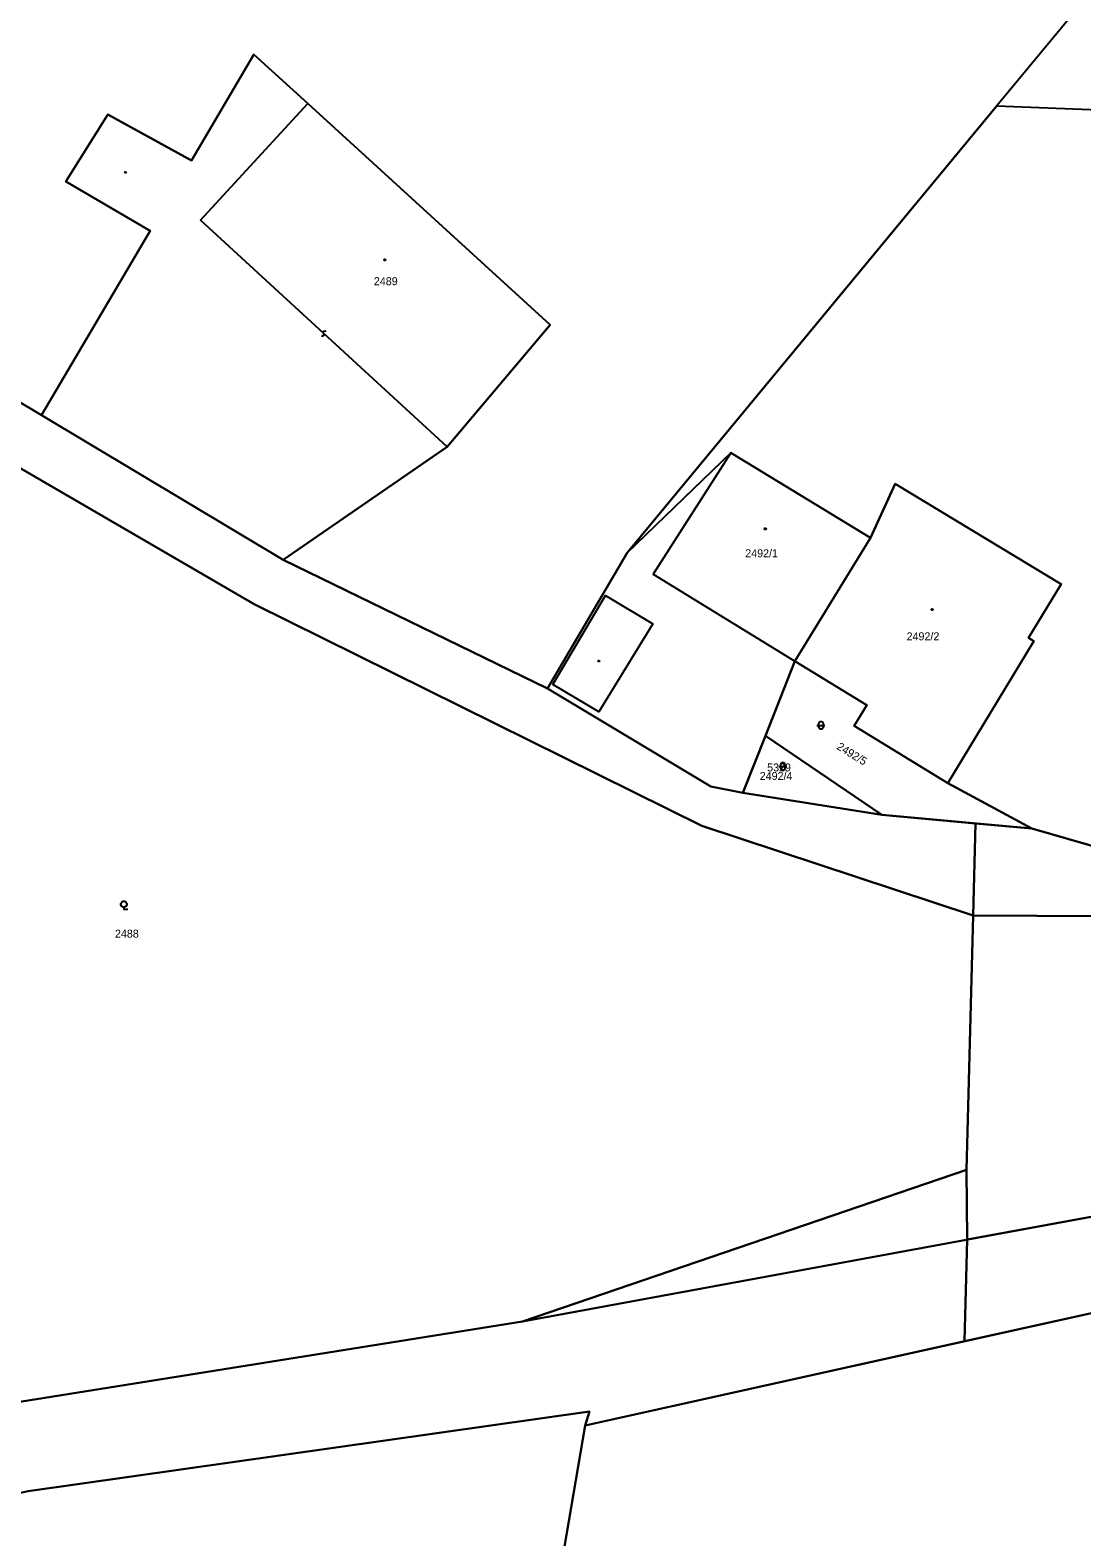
# Model space of a CAD drawing. Extents: x -439750 to -439180, y -1258684 to -1258308.
# Drawn here: x -439415 to -439362.4, y -1258429.7 to -1258354.4 of the extents above; entities that cross this region are included whole.
import ezdxf

# ---------------------------------------------------------------- set-up
doc = ezdxf.new("R2010")
doc.units = 0
doc.layers.add('KATASTER', color=7, linetype='Continuous')
doc.layers.add('UOV', color=7, linetype='Continuous')

# ---------------------------------------------------------------- blocks, each defined once
blk = doc.blocks.new('305')
blk.add_lwpolyline([(0, 0.53), (-0.19, 0.53), (-0.53, 0.72), (-0.72, 1.06), (-0.72, 1.45), (-0.53, 1.79), (-0.19, 1.98), (0.2, 1.98), (0.54, 1.79), (0.73, 1.45), (0.73, 1.06), (0.54, 0.72), (0.2, 0.53), (0.01, 0.53), (0.01, 0), (1.01, 0)])
blk = doc.blocks.new('402')
blk.add_lwpolyline([(0.09, 0.15), (0.18, 0), (0.09, -0.15), (-0.09, -0.15), (-0.18, 0), (-0.09, 0.15), (0.09, 0.15)])
blk = doc.blocks.new('316')
for points in [[(-1, 1), (0.27, 1), (1, 1)], [(-0.5, 1.5), (-0.4, 1.79), (-0.15, 1.97), (0.16, 1.97), (0.41, 1.79), (0.51, 1.5), (0.51, 0.5), (0.41, 0.21), (0.16, 0.03), (-0.15, 0.03), (-0.4, 0.21), (-0.5, 0.5), (-0.5, 1.5)]]:
    blk.add_lwpolyline(points)
blk = doc.blocks.new('2182')
blk.add_lwpolyline([(0.05, 0.75), (-0.26, 0.64), (-0.37, 0.34), (-0.23, 0.09), (0.27, -0.11), (0.37, -0.41), (0.21, -0.68), (-0.05, -0.75)])

msp = doc.modelspace()

# ---------------------------------------------------------------- linework, layer by layer
at = {"layer": 'KATASTER'}
for p, q in [((-439406.44, -1258363.89), (-439401.08, -1258358.06)), ((-439394.11, -1258375.22), (-439406.44, -1258363.89))]:
    msp.add_line(p, q, dxfattribs=at)
for points in [[(-439415.15, -1258317.05), (-439391.19, -1258328.53), (-439365.48, -1258348.34), (-439361.22, -1258351.62), (-439366.64, -1258358.17), (-439385.11, -1258380.51), (-439389.09, -1258387.3), (-439402.31, -1258380.87), (-439394.11, -1258375.22), (-439388.96, -1258369.12), (-439401.08, -1258358.06), (-439403.77, -1258355.61), (-439406.89, -1258360.91), (-439411.07, -1258358.61), (-439413.17, -1258361.96), (-439408.96, -1258364.43), (-439414.38, -1258373.64), (-439426.53, -1258366.38)], [(-439583.01, -1258405.44), (-439529.05, -1258372.98), (-439510.66, -1258363.93), (-439469.66, -1258359.58), (-439457.56, -1258358.3), (-439442.28, -1258360.05), (-439426.53, -1258366.38), (-439414.38, -1258373.64), (-439402.31, -1258380.87), (-439389.09, -1258387.3), (-439380.93, -1258392.19), (-439379.33, -1258392.51), (-439372.39, -1258393.61), (-439364.9, -1258394.3), (-439360.22, -1258395.64), (-439331.05, -1258396.01), (-439324.92, -1258395.23), (-439316.1, -1258393.08), (-439301.55, -1258387.38)], [(-439269.36, -1258377.15), (-439315.05, -1258395.8), (-439324.38, -1258397.9), (-439329.65, -1258398.85), (-439367.83, -1258398.64), (-439381.39, -1258394.16), (-439403.76, -1258383.09), (-439428.41, -1258368.76), (-439442.76, -1258364.07), (-439458.37, -1258362.23), (-439513.27, -1258367.25), (-439515.07, -1258371.54), (-439519.61, -1258372.16), (-439523.86, -1258373.74), (-439527.84, -1258376.06), (-439569.67, -1258401.31)], [(-439379.94, -1258375.52), (-439383.81, -1258381.59), (-439376.73, -1258385.93)], [(-439547.65, -1258418.05), (-439537.73, -1258410.35), (-439527.28, -1258405.47), (-439520.18, -1258404.63), (-439512.57, -1258405.64), (-439506.61, -1258407.45), (-439484.43, -1258417.81), (-439474.81, -1258422.32), (-439466.86, -1258425.16), (-439456.86, -1258427.2), (-439444.81, -1258427.42), (-439422.62, -1258423.93), (-439418.29, -1258423.4), (-439390.34, -1258418.93), (-439355.32, -1258412.49), (-439342.07, -1258411.63), (-439307.35, -1258399.88)], [(-439304.03, -1258403.29), (-439334.89, -1258413.69), (-439341.3, -1258415.85), (-439354.3, -1258417.7), (-439355.78, -1258417.92), (-439355.89, -1258417.18), (-439387.21, -1258424.13), (-439387, -1258423.44), (-439415.05, -1258427.42), (-439434.74, -1258431.72), (-439442.45, -1258432.5), (-439453.89, -1258431.74), (-439461.05, -1258431.03), (-439498.8, -1258414.92), (-439505.79, -1258411.63), (-439510.78, -1258409.92), (-439521.49, -1258405.8), (-439531.73, -1258411.37), (-439536.05, -1258413.64), (-439546.05, -1258421.31)], [(-439342.84, -1258481.76), (-439376.6, -1258488.12), (-439398.93, -1258492.76), (-439393.11, -1258458.67), (-439387.21, -1258424.13), (-439355.89, -1258417.18), (-439355.78, -1258417.92), (-439352.04, -1258443.07), (-439355.61, -1258442.12), (-439357.86, -1258441.52), (-439357.71, -1258440.96), (-439364.32, -1258439.2), (-439364.24, -1258438.91), (-439373.38, -1258436.31), (-439372.9, -1258433.44), (-439378.54, -1258432.5), (-439378.83, -1258437.55), (-439380.62, -1258447.31), (-439375.42, -1258449.5)]]:
    msp.add_lwpolyline(points, dxfattribs=at)
for points in [[(-439414.38, -1258373.64), (-439408.96, -1258364.43), (-439413.17, -1258361.96), (-439411.07, -1258358.61), (-439406.89, -1258360.91), (-439403.77, -1258355.61), (-439401.08, -1258358.06), (-439388.96, -1258369.12), (-439394.11, -1258375.22), (-439402.31, -1258380.87)], [(-439366.64, -1258358.17), (-439356.47, -1258358.58), (-439353.45, -1258359.6), (-439355.3, -1258367), (-439348.37, -1258369.41), (-439336.92, -1258372.08), (-439328.8, -1258373.21), (-439324.08, -1258371.11), (-439318.67, -1258370.58), (-439316.03, -1258371.29), (-439316.73, -1258378.56), (-439318.87, -1258379.92), (-439333.16, -1258382.13), (-439354.32, -1258378.96), (-439360.22, -1258395.64), (-439364.9, -1258394.3), (-439369.09, -1258392.03), (-439364.8, -1258384.93), (-439365.06, -1258384.77), (-439363.43, -1258382.08), (-439371.73, -1258377.06), (-439372.95, -1258379.77), (-439379.94, -1258375.52), (-439385.11, -1258380.51)], [(-439418.29, -1258423.4), (-439428.73, -1258408.86), (-439436.27, -1258398.27), (-439433.21, -1258391.81), (-439448.48, -1258384.63), (-439451.43, -1258391.1), (-439444.69, -1258394.29), (-439445.8, -1258396.64), (-439441.57, -1258398.64), (-439431.25, -1258409.67), (-439422.62, -1258423.93), (-439444.81, -1258427.42), (-439456.86, -1258427.2), (-439466.86, -1258425.16), (-439474.81, -1258422.32), (-439484.43, -1258417.81), (-439458.37, -1258362.23), (-439442.76, -1258364.07), (-439428.41, -1258368.76), (-439403.76, -1258383.09), (-439381.39, -1258394.16), (-439367.83, -1258398.64), (-439368.16, -1258411.35), (-439390.34, -1258418.93)], [(-439372.95, -1258379.77), (-439376.73, -1258385.93), (-439378.2, -1258389.67), (-439379.33, -1258392.51), (-439380.93, -1258392.19), (-439389.09, -1258387.3), (-439385.11, -1258380.51), (-439379.94, -1258375.52)], [(-439269.36, -1258377.15), (-439273.57, -1258384.75), (-439276.5, -1258386.89), (-439278.27, -1258383.72), (-439283.57, -1258386.62), (-439281.42, -1258390.47), (-439287.8, -1258395.11), (-439307.35, -1258399.88), (-439342.07, -1258411.63), (-439355.32, -1258412.49), (-439390.34, -1258418.93), (-439368.16, -1258411.35), (-439367.83, -1258398.64), (-439329.65, -1258398.85), (-439324.38, -1258397.9), (-439315.05, -1258395.8)], [(-439376.73, -1258385.93), (-439372.95, -1258379.77), (-439371.73, -1258377.06), (-439363.43, -1258382.08), (-439365.06, -1258384.77), (-439364.8, -1258384.93), (-439369.09, -1258392.03), (-439373.77, -1258389.16), (-439373.14, -1258388.13)], [(-439388.83, -1258387.1), (-439386.2, -1258382.65), (-439383.83, -1258384.06), (-439386.53, -1258388.46)], [(-439378.2, -1258389.67), (-439376.73, -1258385.93), (-439373.14, -1258388.13), (-439373.77, -1258389.16), (-439369.09, -1258392.03), (-439364.9, -1258394.3), (-439372.39, -1258393.61)], [(-439378.2, -1258389.67), (-439372.39, -1258393.61), (-439379.33, -1258392.51)], [(-439441.83, -1258441.42), (-439442.45, -1258432.5), (-439434.74, -1258431.72), (-439415.05, -1258427.42), (-439387, -1258423.44), (-439387.21, -1258424.13), (-439393.11, -1258458.67), (-439398.93, -1258492.76), (-439399.2, -1258493.87), (-439399.61, -1258493.83), (-439469.01, -1258485.93), (-439465.13, -1258459.21), (-439462.74, -1258442.73), (-439442, -1258444.33)]]:
    msp.add_lwpolyline(points, close=True, dxfattribs=at)
at = {"layer": 'UOV'}
for points in [[(-439301.55, -1258387.38), (-439316.1, -1258393.08), (-439324.92, -1258395.23), (-439331.05, -1258396.01), (-439360.22, -1258395.64), (-439364.9, -1258394.3), (-439367.7, -1258394.04), (-439372.39, -1258393.61), (-439378.2, -1258389.67), (-439379.33, -1258392.51), (-439380.93, -1258392.19), (-439389.09, -1258387.3), (-439402.31, -1258380.87), (-439414.38, -1258373.64), (-439426.53, -1258366.38), (-439442.28, -1258360.05), (-439457.56, -1258358.3), (-439510.66, -1258363.93), (-439529.05, -1258372.98), (-439583.01, -1258405.44)], [(-439307.35, -1258399.88), (-439342.07, -1258411.63), (-439355.32, -1258412.49), (-439368.12, -1258414.84), (-439368.16, -1258411.35), (-439367.83, -1258398.64), (-439367.7, -1258394.04), (-439364.9, -1258394.3), (-439360.22, -1258395.64), (-439331.05, -1258396.01), (-439324.92, -1258395.23), (-439316.1, -1258393.08), (-439301.55, -1258387.38)], [(-439418.29, -1258423.4), (-439390.34, -1258418.93), (-439368.16, -1258411.35), (-439368.12, -1258414.84), (-439368.25, -1258419.92), (-439387.21, -1258424.13), (-439387, -1258423.44), (-439415.05, -1258427.42)]]:
    msp.add_lwpolyline(points, dxfattribs=at)
for points in [[(-439510.66, -1258363.93), (-439457.56, -1258358.3), (-439442.28, -1258360.05), (-439426.53, -1258366.38), (-439414.38, -1258373.64), (-439402.31, -1258380.87), (-439389.09, -1258387.3), (-439380.93, -1258392.19), (-439379.33, -1258392.51), (-439372.39, -1258393.61), (-439367.7, -1258394.04), (-439367.83, -1258398.64), (-439381.39, -1258394.16), (-439403.76, -1258383.09), (-439428.41, -1258368.76), (-439442.76, -1258364.07), (-439458.37, -1258362.23), (-439472.18, -1258363.49), (-439510.27, -1258366.98)], [(-439304.03, -1258403.29), (-439341.3, -1258415.85), (-439354.3, -1258417.7), (-439355.78, -1258417.92), (-439355.89, -1258417.18), (-439368.25, -1258419.92), (-439368.12, -1258414.84), (-439355.32, -1258412.49), (-439342.07, -1258411.63), (-439307.35, -1258399.88), (-439287.8, -1258395.11), (-439279.12, -1258394.03), (-439277.15, -1258393.78), (-439252.22, -1258388.27), (-439241.48, -1258387.75), (-439250.33, -1258391.52), (-439274.68, -1258396.43)], [(-439379.33, -1258392.51), (-439378.2, -1258389.67), (-439372.39, -1258393.61)]]:
    msp.add_lwpolyline(points, close=True, dxfattribs=at)

# ---------------------------------------------------------------- block references
at = {"layer": 'KATASTER', "xscale": 0.2, "yscale": 0.20000000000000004}
for name, p in [('402', (-439410.19, -1258361.5)), ('402', (-439397.23, -1258365.87)), ('402', (-439378.21, -1258379.32)), ('402', (-439369.88, -1258383.35)), ('402', (-439386.53, -1258385.92)), ('316', (-439375.43, -1258389.34)), ('316', (-439377.33, -1258391.39)), ('305', (-439410.27, -1258398.33))]:
    msp.add_blockref(name, p, dxfattribs=at)
at = {"layer": 'KATASTER', "xscale": 0.2, "yscale": 0.20000000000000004, "rotation": 137.39527900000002}
msp.add_blockref('2182', (-439400.275, -1258369.555), dxfattribs=at)

# ---------------------------------------------------------------- texts
at = {"layer": 'KATASTER'}
for s, p in [('2489', (-439397.772, -1258367.14)), ('2492/1', (-439379.215, -1258380.74)), ('2492/2', (-439371.152, -1258384.89)), ('2492/4', (-439378.491, -1258391.87)), ('2488', (-439410.712, -1258399.75))]:
    msp.add_text(s, height=0.4, dxfattribs=at).set_placement(p)
msp.add_text('2492/5', height=0.4, rotation=328.419, dxfattribs=at).set_placement((-439374.679, -1258390.302))
at = {"layer": 'UOV'}
msp.add_text('5329', height=0.4, dxfattribs=at).set_placement((-439378.121, -1258391.443))

doc.saveas('drawing.dxf')
